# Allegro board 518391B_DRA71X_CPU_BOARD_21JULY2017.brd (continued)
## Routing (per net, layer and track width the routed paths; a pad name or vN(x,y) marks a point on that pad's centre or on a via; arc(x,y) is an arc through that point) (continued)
H_DDR1_D13: length 31.5
  TOP w0.102: U23.D7 v4(62.55,93)
  TOP w0.127: v2(78.63,90.33) 78.65,90.33 78.77,90.45 79.98,90.45 80.09,90.56 U27.AB25
  LY4 w0.133: v4(62.55,93) 62.55,93.36 62.8,93.61 62.8,93.95 62.55,94.2 62.55,94.45 62.84,94.74 63.09,94.74 63.45,94.39 63.88,94.39 64.24,94.74 64.59,94.74 64.9,94.44 65.43,94.44 65.74,94.74 66.01,94.74 66.32,94.44 66.32,94.09 66.45,93.95 70.23,93.95 71.98,92.2 71.98,90.83 71.53,90.37 71.53,90.12 71.66,89.99 72.41,89.99 72.54,90.12 72.54,90.75 72.68,90.88 72.92,90.88 73.04,90.77 73.04,90.34 73.15,90.22 73.43,90.22 73.58,90.37 73.58,90.55 73.89,90.86 74.16,90.86 74.59,90.42 78.11,90.42 78.2,90.33 v2(78.63,90.33)
H_DDR1_D14: length 31.2
  TOP w0.102: U23.A3 v4(64.95,97)
  TOP w0.127: v2(80.01,90.02) 80.33,89.7 81.29,89.7 81.5,89.91 U27.AA25
  LY4 w0.133: v4(64.95,97) 65.36,97.41 65.67,97.41 65.8,97.28 65.8,96.91 65.93,96.77 66.2,96.77 66.33,96.91 66.33,97.28 66.46,97.41 66.72,97.41 66.86,97.28 66.86,96.91 66.99,96.77 67.25,96.77 67.38,96.91 67.38,97.28 67.52,97.41 67.78,97.41 67.91,97.28 67.91,96.91 68.04,96.77 68.31,96.77 68.44,96.91 68.44,97.28 68.57,97.41 68.84,97.41 68.97,97.28 68.97,96.91 69.1,96.77 69.37,96.77 69.5,96.91 69.5,97.28 69.63,97.41 69.89,97.41 70.03,97.28 70.03,96.91 70.16,96.77 70.42,96.77 70.55,96.91 70.55,97.28 70.69,97.41 74.8,97.41 75.01,97.21 75.01,96.8 75.14,96.67 76.48,96.67 76.68,96.47 76.68,95.63 77.37,94.95 77.37,94.08 78.36,93.09 78.46,93.09 79.63,91.92 79.63,91.14 80.01,90.75 v2(80.01,90.02)
H_DDR1_D15: length 31.2
  TOP w0.102: U27.W24 85.49,88.29 85.49,88.28 84.4,88.28 ; U23.C2 v4(63.35,97.8)
  TOP w0.127: v2(81,88.16) 81.42,88.16 81.55,88.28 84.4,88.28
  LY4 w0.133: v4(63.35,97.8) 63.75,98.19 76.89,98.19 78.36,96.72 78.36,95.12 81.28,92.2 81.28,88.44 v2(81,88.16)
H_DDR1_D16: length 39.3
  TOP w0.102: U29.F8 v4(60.95,77.97)
  TOP w0.127: U27.W23 v1(86.14,88.28)
  LY4 w0.133: v4(60.95,77.97) 60.55,78.37 59.16,78.37 58.88,78.65 58.88,79.68 58.42,80.14 58.42,84.84 60.64,87.06 65.17,87.06 65.87,87.76 71.93,87.76 72.14,87.96 80.01,87.96 80.55,87.42 81.69,87.42 82.54,88.27 v1(86.14,88.28)
H_DDR1_D17: length 44
  TOP w0.102: U29.H8 v4(59.35,77.97)
  TOP w0.127: v2(74.55,84.07) 74.55,85.82 74.94,86.21 75.92,86.21 76.2,85.93 76.7,85.93 77.3,86.53 81.2,86.53 81.2,86.52 81.55,86.52 81.56,86.53 82.44,86.53 83.22,87.31 U27.U25
  LY3 w0.133: v2(74.55,84.07) 74.34,83.87 74.34,82.6 74.04,82.3 73.61,82.3 73.33,82.58 73.33,83.06 73.1,83.29 69.85,83.29 69.67,83.11 69.67,82.53 69.47,82.32 68.95,82.32 68.67,82.6 68.67,83.02 68.5,83.19 67.94,83.19 67.67,82.91 67.67,82.4 67.26,81.99 66.17,81.99 65.91,81.74 62.89,81.74 62.43,82.19 59.41,82.19 59.08,81.86 59.08,79.51 59.24,79.35 59.56,79.35 59.72,79.51 59.72,81.61 59.87,81.76 60.17,81.76 60.33,81.61 60.33,79.61 59.75,79.03 59.75,78.37 v4(59.35,77.97)
H_DDR1_D18: length 44.5
  TOP w0.102: U29.F7 v4(60.95,78.77) ; 84.4,86.98 85.49,86.98 85.49,86.99 U27.U24
  TOP w0.127: 84.4,86.98 83.38,86.98 82.67,86.28 81.67,86.28 81.66,86.27 81.1,86.27 81.09,86.28 77.54,86.28 76.94,85.68 75.97,85.68 75.72,85.93 75.34,85.93 75.13,85.72 75.13,84.91 75.21,84.84 75.44,84.84 75.9,85.29 76.2,85.29 76.3,85.19 76.3,85.04 75.09,83.83 75.09,82.2 v2(74.55,81.66)
  LY3 w0.133: v4(60.95,78.77) 60.55,78.37 60.55,76.84 60.83,76.56 62.74,76.56 62.94,76.76 62.94,77.01 62.94,77.01 62.94,78.94 62.94,78.94 62.94,79.13 62.74,79.33 62.74,80.67 63.12,81.05 66.42,81.05 66.75,81.38 67.87,81.38 68.15,81.66 70.35,81.66 70.48,81.53 70.48,81.2 70.38,81.1 69.01,81.1 68.81,80.9 68.81,80.72 69.01,80.52 72.52,80.52 72.75,80.75 74.27,80.75 74.55,81.03 v2(74.55,81.66)
H_DDR1_D19: length 42.8
  TOP w0.102: U29.F2 v4(60.95,83.57)
  TOP w0.127: U27.W21 v1(87.44,88.28)
  LY3 w0.133: v4(60.95,83.57) 60.54,83.97 60.54,84.8 61.09,85.34 61.09,86.05 61.62,86.58 61.62,88.24 62.41,89.03 64.49,89.03 65.27,89.8 65.6,89.8 65.73,89.67 65.73,89.34 65.87,89.2 66.13,89.2 66.26,89.34 66.26,89.67 66.39,89.8 66.66,89.8 66.79,89.67 66.79,89.34 66.92,89.2 67.19,89.2 67.32,89.34 67.32,89.67 67.51,89.87 70.94,89.87 71.57,89.24 79.14,89.24 79.65,88.72 80.19,88.72 80.32,88.85 80.32,89.5 80.46,89.64 80.72,89.64 80.85,89.5 80.85,88.85 80.98,88.72 81.25,88.72 81.38,88.85 81.38,89.5 81.51,89.64 81.78,89.64 81.91,89.5 81.91,88.85 82.04,88.72 82.3,88.72 82.44,88.85 82.44,89.5 82.57,89.64 82.83,89.64 82.96,89.5 82.96,88.85 83.1,88.72 83.36,88.72 83.49,88.85 83.49,89.5 83.62,89.64 83.89,89.64 84.02,89.5 84.02,88.85 84.15,88.72 84.42,88.72 84.55,88.85 84.55,89.5 84.68,89.64 84.95,89.64 85.08,89.5 85.08,88.91 85.21,88.78 86.95,88.78 v1(87.44,88.28)
H_DDR1_D20: length 42.4
  TOP w0.102: U29.E3 v4(61.75,82.77)
  TOP w0.127: U27.T22 v1(86.79,86.33)
  LY3 w0.133: v1(86.79,86.33) 87.16,86.71 87.59,86.71 87.82,86.93 87.82,87.12 87.69,87.25 87,87.25 86.49,86.74 85.25,86.74 85.12,86.87 85.12,87.29 84.98,87.43 84.61,87.43 84.4,87.22 84.4,86.51 84.21,86.31 83.94,86.31 83.77,86.49 83.77,87.35 83.67,87.45 83.35,87.45 83.22,87.32 83.22,86.52 83.09,86.39 82.82,86.39 82.55,86.66 82.55,87.13 82.23,87.45 81.8,87.45 81.72,87.36 81.11,87.36 81,87.25 80.39,87.25 80.14,86.99 78.69,86.99 78.56,87.13 78.56,87.31 78.66,87.41 79.27,87.41 79.4,87.54 79.4,87.73 79.28,87.85 72.84,87.85 72.45,87.46 65.97,87.46 65.34,86.83 63.85,86.83 63.63,86.62 63.63,85.07 63.48,84.91 63.3,84.91 63.17,85.04 63.17,86.61 63.02,86.76 62.84,86.76 62.59,86.51 62.59,85.55 62.15,85.11 62.15,83.17 v4(61.75,82.77)
H_DDR1_D21: length 42.5
  TOP w0.102: U29.G2 v4(60.15,83.57)
  TOP w0.127: U27.U22 v1(86.79,87.63)
  LY3 w0.133: v1(86.79,87.63) 86.33,87.17 85.83,87.17 84.81,88.19 81.87,88.19 81.74,88.06 81.74,87.84 81.61,87.71 80.11,87.71 79.65,88.17 72.57,88.17 72.14,87.73 70.98,87.73 70.85,87.86 70.85,88.77 70.72,88.9 70.45,88.9 70.32,88.77 70.32,87.86 70.19,87.73 69.93,87.73 69.79,87.86 69.79,88.77 69.66,88.9 69.4,88.9 69.27,88.77 69.27,87.86 69.13,87.73 68.87,87.73 68.74,87.86 68.74,88.77 68.61,88.9 68.34,88.9 68.21,88.77 68.21,87.86 68.08,87.73 67.81,87.73 67.68,87.86 67.68,88.77 67.55,88.9 67.28,88.9 67.15,88.77 67.15,87.86 67.02,87.73 66.76,87.73 66.62,87.86 66.62,88.77 66.49,88.9 66.23,88.9 66.1,88.77 66.1,88 65.19,87.1 62.63,87.1 61.35,85.81 61.35,83.39 61.13,83.17 60.55,83.17 v4(60.15,83.57)
H_DDR1_D22: length 39.1
  TOP w0.102: U29.H7 v4(59.35,78.77)
  TOP w0.127: U27.U23 v1(86.14,87.63)
  LY4 w0.133: v1(86.14,87.63) 85.7,87.19 85.41,87.19 85.23,87.37 85.23,87.8 85.07,87.96 84.86,87.96 84.7,87.8 84.7,87.28 84.57,87.15 84.28,87.15 84.1,87.33 84.1,87.68 83.97,87.81 83.49,87.81 83.34,87.66 83.34,86.89 82.89,86.45 80.89,86.45 79.68,87.66 72.42,87.66 72.23,87.47 66,87.47 65.22,86.69 60.75,86.69 58.8,84.73 58.8,80.39 59.35,79.84 v4(59.35,78.77)
H_DDR1_D23: length 39.2
  TOP w0.102: U29.H3 v4(59.35,82.77)
  TOP w0.127: U27.T21 v1(87.44,86.33)
  LY4 w0.133: v1(87.44,86.33) 87.03,86.74 84.68,86.74 83.42,85.47 83.23,85.47 83.05,85.65 82.86,85.65 82.67,85.47 82.67,85.28 82.85,85.1 82.85,84.91 82.67,84.72 81.4,84.72 81.27,84.86 81.27,85.29 81.14,85.42 80.87,85.42 80.74,85.29 80.74,84.86 80.61,84.72 80.34,84.72 80.21,84.86 80.21,85.29 80.08,85.42 79.82,85.42 79.68,85.29 79.68,84.86 79.55,84.72 79.29,84.72 79.16,84.86 79.16,85.29 79.02,85.42 78.76,85.42 78.63,85.29 78.63,84.86 78.49,84.72 78.23,84.72 78.1,84.86 77.57,84.86 77.44,84.72 67.81,84.72 67.45,84.37 67.45,81.78 66.45,80.77 59.66,80.77 59.35,81.09 v4(59.35,82.77)
H_DDR1_D24: length 31.3
  TOP w0.102: U29.C3 v4(63.35,82.77)
  TOP w0.127: U27.T23 v1(86.14,86.33)
  LY3 w0.133: v4(63.35,82.77) 62.95,83.17 62.95,83.75 63.16,83.97 64.38,83.97 64.55,84.14 64.55,84.59 64.77,84.81 65.15,84.81 65.28,84.94 65.28,85.33 65.14,85.46 64.75,85.46 64.54,85.67 64.54,86.18 64.92,86.57 66.51,86.57 67.07,87.12 72.57,87.12 72.92,87.48 75.69,87.48 75.92,87.25 75.92,86.92 76.05,86.79 76.68,86.79 76.89,86.99 76.89,87.33 77.09,87.53 77.7,87.53 77.93,87.3 77.93,86.66 78.08,86.51 82.14,86.51 82.65,86 84.43,86 84.75,86.33 v1(86.14,86.33)
H_DDR1_D25: length 32.6
  TOP w0.102: U29.A7 v4(64.95,78.77)
  TOP w0.127: U27.T25 84.42,86.66 84.35,86.59 83.36,86.59 82.8,86.02 81.77,86.02 81.76,86.01 80.99,86.01 80.98,86.02 77.77,86.02 75.69,83.95 v2(75.69,82.68)
  LY3 w0.133: v4(64.95,78.77) 65.27,79.1 66.74,79.1 66.87,79.23 66.87,79.67 67,79.81 67.27,79.81 67.4,79.67 67.4,79.23 67.53,79.1 67.8,79.1 67.93,79.23 67.93,79.67 68.06,79.81 68.32,79.81 68.46,79.67 68.46,79.23 68.59,79.1 68.85,79.1 68.98,79.23 68.98,79.67 69.12,79.81 69.38,79.81 69.51,79.67 69.51,79.23 69.64,79.1 69.91,79.1 70.04,79.23 70.04,79.67 70.17,79.81 70.44,79.81 70.57,79.67 70.57,79.23 70.7,79.1 70.97,79.1 71.1,79.23 71.1,79.67 71.23,79.81 71.49,79.81 71.63,79.67 71.63,79.23 71.76,79.1 72.02,79.1 72.15,79.23 72.15,79.67 72.29,79.81 72.55,79.81 72.68,79.67 72.68,79.23 72.81,79.1 74.02,79.1 75.18,80.26 75.18,82.17 v2(75.69,82.68)
H_DDR1_D26: length 32.6
  TOP w0.102: U29.B8 v4(64.15,77.97) ; 84.4,86.33 85.49,86.33 U27.T24
  TOP w0.127: v2(75.68,81.8) 76.2,82.32 76.2,84.1 77.87,85.77 80.88,85.77 80.89,85.76 81.87,85.76 81.88,85.77 82.95,85.77 83.51,86.33 84.4,86.33
  LY3 w0.133: v4(64.15,77.97) 64.55,77.57 66.71,77.57 66.85,77.7 66.85,77.87 66.98,78 67.25,78 67.38,77.87 67.38,77.19 67.51,77.06 67.78,77.06 67.91,77.19 67.91,77.87 68.05,78 68.31,78 68.45,77.87 68.45,77.7 68.58,77.57 68.85,77.57 68.98,77.7 68.98,77.87 69.11,78 69.38,78 69.51,77.87 69.51,77.7 69.65,77.57 69.91,77.57 70.05,77.7 70.05,77.87 70.18,78 70.45,78 70.58,77.87 70.58,77.7 70.71,77.57 70.98,77.57 71.11,77.7 71.11,77.87 71.25,78 71.51,78 71.65,77.87 71.65,77.7 71.78,77.57 72.05,77.57 72.18,77.7 72.18,77.87 72.31,78 72.58,78 72.71,77.87 72.71,77.7 72.85,77.57 73.25,77.57 75.68,80 v2(75.68,81.8)
H_DDR1_D27: length 31.2
  TOP w0.102: U29.A3 v4(64.95,82.77)
  TOP w0.127: U27.P21 v1(87.44,85.68)
  LY3 w0.133: v4(64.95,82.77) 65.61,82.77 67.26,84.42 67.26,84.79 67.69,85.22 69.46,85.22 69.6,85.35 69.6,85.54 69.43,85.71 67.52,85.71 67.39,85.84 67.39,86.02 67.52,86.16 72.11,86.16 72.29,85.98 72.29,85.45 72.57,85.17 77.27,85.17 77.72,85.62 81.48,85.62 82.08,85.02 86.78,85.02 v1(87.44,85.68)
H_DDR1_D28: length 28.2
  TOP w0.102: U29.C8 v4(63.35,77.97)
  TOP w0.127: U27.N21 v1(87.44,84.38)
  LY4 w0.133: v4(63.35,77.97) 64.02,78.37 65.06,78.37 66.41,78.87 74.68,78.87 80.01,84.2 82.8,84.2 83.7,85.09 86.73,85.09 v1(87.44,84.38)
H_DDR1_D29: length 31.3
  TOP w0.102: U29.C2 v4(63.35,83.57)
  TOP w0.127: U27.P22 v1(86.79,85.68)
  LY3 w0.133: v1(86.79,85.68) 86.4,85.28 82.36,85.28 81.71,85.93 77.52,85.93 77.24,85.65 72.92,85.65 72.8,85.78 72.8,85.93 72.92,86.06 74.3,86.06 74.45,86.21 74.45,86.36 74.31,86.5 67.3,86.5 66.93,86.13 66.93,84.54 65.56,83.17 63.75,83.17 v4(63.35,83.57)
H_DDR1_D30: length 31.3
  TOP w0.102: U29.A2 v4(64.95,83.57)
  TOP w0.127: U27.P23 v1(86.14,85.68)
  LY3 w0.133: v4(64.95,83.57) 65.56,83.57 66.6,84.61 66.6,85.75 66.47,85.88 66.22,85.88 66.09,85.75 66.09,84.8 65.92,84.63 65.74,84.63 65.58,84.79 65.58,85.87 66,86.29 66.62,86.29 67.15,86.82 72.9,86.82 73.23,87.15 75.41,87.15 75.56,86.99 75.56,86.66 75.46,86.56 74.96,86.56 74.85,86.46 74.85,86.06 75,85.91 76.99,85.91 77.32,86.23 81.94,86.23 82.43,85.74 v1(86.14,85.68)
H_DDR1_D31: length 29.2
  TOP w0.102: 84.4,84.82 84.62,85.03 85.49,85.03 U27.P24 ; U29.D7 v4(62.55,78.77)
  TOP w0.127: v2(77.45,83.29) 77.98,83.82 78.49,83.82 79.12,84.45 84.04,84.45 84.4,84.82
  LY4 w0.133: v4(62.55,78.77) 62.55,79.67 62.99,80.11 67.08,80.11 67.74,80.77 67.74,81.25 68.68,82.19 68.68,82.91 69.16,83.39 71.04,83.39 71.5,82.93 71.5,82.49 71.69,82.3 73.03,82.3 73.28,82.55 73.28,82.93 73.64,83.29 v2(77.45,83.29)
H_DDR1_DQM0: length 33.4
  TOP w0.102: U23.E7 v4(61.75,93)
  TOP w0.127: U27.AE23 86.46,93.37 85.45,94.39 v2(84.15,94.39)
  LY3 w0.133: v2(84.15,94.39) 85.47,94.39 85.62,94.24 85.62,93.55 85.49,93.42 84.18,93.42 83.41,92.66 83.41,91.82 83.06,91.47 82.4,91.47 81.66,92.2 80.92,92.2 80.49,91.77 79.45,91.77 77.6,93.62 61.9,93.62 61.75,93.47 v4(61.75,93)
H_DDR1_DQM1: length 30.7
  TOP w0.102: U23.D3 v4(62.55,97)
  TOP w0.127: U27.W22 v1(86.79,88.28)
  LY4 w0.133: v1(86.79,88.28) 86.29,88.79 82.42,88.79 81.35,87.72 80.84,87.72 79.45,89.1 79.45,90.12 78.79,90.78 77.62,90.78 77.22,91.19 77.22,91.41 72.72,95.91 63.2,95.91 62.55,96.56 v4(62.55,97)
H_DDR1_DQM2: length 42.4
  TOP w0.102: U29.E7 v4(61.75,78.77)
  TOP w0.127: U27.U21 v1(88.09,87.63)
  LY3 w0.133: v1(88.09,87.63) 88.27,87.46 88.27,86.68 88.46,86.49 88.46,85.53 87.72,84.79 84.54,84.79 84.51,84.76 82.6,84.76 81.72,83.88 75.63,83.88 74.8,83.06 74.8,82.54 73.87,81.6 72.76,81.6 72.34,81.18 71.08,81.18 70.94,81.31 70.94,81.58 71.08,81.71 72.03,81.71 72.14,81.81 72.14,82.06 72,82.19 70.03,82.19 69.77,81.94 67.82,81.94 67.56,81.69 66.4,81.69 66.07,81.36 62.71,81.36 62.23,81.84 60.83,81.84 60.73,81.74 60.73,80.92 60.91,80.75 61.75,80.75 61.88,80.61 61.88,80.37 61.74,80.23 60.98,80.23 60.79,80.04 60.79,79.76 60.92,79.63 61.54,79.63 61.75,79.43 v4(61.75,78.77)
H_DDR1_DQM3: length 32.1
  TOP w0.102: U29.D3 v4(62.55,82.77)
  TOP w0.127: v2(78.13,84.3) 78.66,84.84 83.9,84.84 84.42,85.36 U27.P25
  LY3 w0.133: v4(62.55,82.77) 63.23,82.09 65.63,82.09 68.25,84.71 77.52,84.71 77.98,85.17 81.1,85.17 81.23,85.03 81.23,84.43 81.1,84.3 v2(78.13,84.3)
H_DDR1_DQS0_N: length 33.4
  TOP w0.102: v2(84.63,95.55) 84.86,95.33 85.55,95.33 87.12,93.76 87.12,92.79 87.12,92.78 87.12,92.51 U27.AE22
  TOP w0.103: U23.G3 v4(60.15,97)
  LY3 w0.102: 85.17,95.43 85.06,95.33 84.86,95.33 v2(84.63,95.55)
  LY3 w0.114: 85.17,95.43 85.17,95.74 84.92,95.99 84.45,95.99 84.18,95.71 83.9,95.71 83.62,95.99 82.93,95.99 82.68,95.73 82.4,95.73 82.14,95.99 78.96,95.99 77.8,94.82 67.7,94.82 67.19,95.33 61.01,95.33 60.35,95.99 60.35,96.79 v4(60.15,97)
H_DDR1_DQS0_P: length 33.7
  TOP w0.102: v2(84.66,94.82) 84.89,95.05 85.36,95.05 86.79,93.62 86.79,92.78
  TOP w0.103: 86.79,92.78 86.79,92.37 87.11,92.04 U27.AD22 ; U23.F3 v4(60.95,97)
  LY3 w0.102: v2(84.66,94.82) 84.66,94.84 84.86,95.05 85.24,95.05
  LY3 w0.114: v4(60.95,97) 60.71,96.75 60.71,96.13 61.16,95.68 67.34,95.68 67.84,95.17 77.65,95.17 78.82,96.34 85.06,96.34 85.47,95.94 85.47,95.28 85.24,95.05
H_DDR1_DQS1_N: length 31.2
  TOP w0.102: U27.Y25 85.16,89.26 84.89,89.26 84.89,89.26 82.17,89.26 82.17,89.26 81.85,89.26 81.72,89.13 80.42,89.13 80.41,89.13 79.23,89.13 v2(78.92,88.82)
  TOP w0.103: U23.B7 v4(64.15,93)
  LY4 w0.114: v4(64.15,93) 63.91,93.24 63.91,93.47 64.03,93.6 65.26,93.6 65.8,93.06 69.92,93.06 71.01,91.96 71.01,91.1 70.36,90.45 69.65,90.45 69.04,89.84 69.04,88.83 69.63,88.24 70.81,88.24 71.72,89.15 72.09,89.15 72.44,88.8 72.75,88.8 73.1,89.15 73.38,89.15 73.66,88.88 73.82,88.88 74.09,89.15 74.3,89.15 74.57,88.88 74.73,88.88 75.01,89.15 78.13,89.15 78.2,89.08 78.36,89.08 78.44,89.15 78.58,89.15 v2(78.92,88.82)
H_DDR1_DQS1_P: length 31.7
  TOP w0.102: U27.Y24 85.49,89.59 85.03,89.59 85.03,89.59 82.03,89.59 82.03,89.59 81.71,89.59 81.58,89.46 79.93,89.46 79.93,89.46 79.15,89.46 v2(78.92,89.7)
  TOP w0.103: U23.C7 v4(63.35,93)
  LY4 w0.114: v2(78.92,89.7) 78.73,89.51 71.58,89.51 70.66,88.6 69.77,88.6 69.39,88.98 69.39,89.69 69.79,90.09 70.51,90.09 71.36,90.95 71.36,92.11 70.06,93.41 65.95,93.41 65.4,93.95 63.89,93.95 63.55,93.62 63.55,93.2 v4(63.35,93)
H_DDR1_DQS2_N: length 40.3
  TOP w0.102: 84.4,87.95 84.43,87.97 84.72,87.97 84.73,87.97 85.15,87.97 U27.V25
  TOP w0.103: U29.G3 v4(60.15,82.77)
  TOP w0.112: v2(76.38,87.23) 77.15,87.23 77.27,87.35 80.54,87.35 80.91,87.72 81.62,87.72 81.83,87.92 84.38,87.92 84.4,87.95
  LY4 w0.114: v2(76.38,87.23) 77.11,87.23 77.72,86.61 77.72,85.82 77.17,85.27 74.42,85.27 74.1,85.59 74.1,86.19 73.99,86.31 73.76,86.31 73.64,86.19 73.64,85.59 73.32,85.27 72.8,85.27 72.48,85.59 72.48,86.19 72.36,86.31 72.13,86.31 72.02,86.19 72.02,85.59 71.7,85.27 71.17,85.27 70.85,85.59 70.85,86.19 70.74,86.31 70.51,86.31 70.39,86.19 70.39,85.59 70.07,85.27 69.55,85.27 69.23,85.59 69.23,86.19 69.03,86.39 68.1,86.39 66.42,84.71 66.42,82.05 65.68,81.31 60.55,81.31 60.15,81.71 v4(60.15,82.77)
H_DDR1_DQS2_P: length 40.5
  TOP w0.102: 85.49,87.64 85.49,87.63 85.33,87.63 85.32,87.62 85.31,87.62 85.31,87.62 85.29,87.62
  TOP w0.103: U27.V24 85.49,87.64 ; U29.F3 v4(60.95,82.77)
  TOP w0.112: v2(76.38,86.35) 76.38,86.69 76.51,86.82 76.55,86.82 76.6,86.88 77.3,86.88 77.41,86.99 80.69,86.99 81.06,87.36 81.77,87.36 81.97,87.57 84.53,87.57 84.58,87.62 85.29,87.62
  LY4 w0.114: v2(76.38,86.35) 76.38,86.66 76.59,86.88 76.96,86.88 77.37,86.47 77.37,85.97 77.03,85.62 74.57,85.62 74.46,85.74 74.46,86.34 74.13,86.66 73.61,86.66 73.29,86.34 73.29,85.74 73.17,85.62 72.95,85.62 72.83,85.74 72.83,86.34 72.51,86.66 71.99,86.66 71.66,86.34 71.66,85.74 71.55,85.62 71.32,85.62 71.21,85.74 71.21,86.34 70.88,86.66 70.36,86.66 70.04,86.34 70.04,85.74 69.92,85.62 69.7,85.62 69.58,85.74 69.58,86.34 69.18,86.74 67.95,86.74 66.07,84.86 66.07,82.19 65.53,81.66 60.7,81.66 60.5,81.86 60.5,82.6 60.67,82.77 v4(60.95,82.77)
H_DDR1_DQS3_N: length 29.6
  TOP w0.102: U27.R25 85.16,86 84.4,86
  TOP w0.103: U29.B7 v4(64.15,78.77)
  TOP w0.112: v2(73.69,81.18) 73.94,80.93 75.54,80.93 76.61,81.99 76.61,83.87 78.25,85.51 83.38,85.51 83.87,86 84.4,86
  LY4 w0.114: v4(64.15,78.77) 63.93,78.99 63.93,79.18 64.05,79.3 74.52,79.3 75.03,79.81 75.03,80.54 74.65,80.93 73.94,80.93 v2(73.69,81.18)
H_DDR1_DQS3_P: length 29.8
  TOP w0.102: U27.R24 85.49,85.69 84.58,85.69 84.54,85.65 84.4,85.65
  TOP w0.103: U29.C7 v4(63.35,78.77)
  TOP w0.112: 84.4,85.65 84.02,85.65 83.53,85.16 78.4,85.16 76.96,83.72 76.96,81.84 75.69,80.57 73.94,80.57 v2(73.69,80.32)
  LY4 w0.114: v4(63.35,78.77) 63.58,79 63.58,79.33 63.9,79.65 74.38,79.65 74.68,79.95 74.68,80.4 74.5,80.57 73.94,80.57 v2(73.69,80.32)
H_DDR1_ODT0: length 103.1
  TOP w0.102: U29.K1 v4(56.95,84.37) ; 90.04,93.24 90.04,92.18 U27.AD18 ; U23.K1 v4(56.95,98.6)
  TOP w0.127: 90.04,93.24 90.04,94.49 89.12,95.41 89.12,96.76 89,96.88 v2(89,98.98)
  LY3 w0.133: v2(89,98.98) 89,97.99 88.77,97.76 87.08,97.76 85.73,99.11 85.73,99.73 85.16,100.29 83.63,100.29 83.02,100.91 82.07,100.91 81.93,100.77 81.93,99.8 81.8,99.66 81.53,99.66 81.4,99.8 81.4,100.77 81.27,100.91 81,100.91 80.87,100.77 80.87,99.8 80.73,99.66 80.47,99.66 80.33,99.8 80.33,100.77 80.2,100.91 79.93,100.91 79.8,100.77 79.8,99.8 79.67,99.66 79.4,99.66 79.27,99.8 79.27,100.77 79.13,100.91 78.87,100.91 78.73,100.77 78.73,99.8 78.6,99.66 78.33,99.66 78.2,99.8 78.2,100.57 77.94,100.84 76.81,100.84 76.67,100.7 76.67,99.8 76.54,99.66 76.27,99.66 76.14,99.8 76.14,100.7 76.01,100.84 75.74,100.84 75.61,100.7 75.61,99.8 75.47,99.66 75.21,99.66 75.07,99.8 75.07,100.7 74.94,100.84 74.67,100.84 74.54,100.7 74.54,99.8 74.41,99.66 74.14,99.66 74.01,99.8 74.01,100.7 73.87,100.84 73.61,100.84 73.47,100.7 73.47,99.8 73.34,99.66 73.07,99.66 72.94,99.8 72.94,100.7 72.81,100.84 69.68,100.84 69.55,100.7 69.55,100.13 69.42,99.99 69.15,99.99 69.02,100.13 69.02,100.7 68.88,100.84 68.62,100.84 68.48,100.7 68.48,100.13 68.35,99.99 68.08,99.99 67.95,100.13 67.95,100.7 67.82,100.84 67.55,100.84 67.42,100.7 67.42,100.13 67.28,99.99 67.02,99.99 66.88,100.13 66.88,100.7 66.75,100.84 66.48,100.84 66.35,100.7 66.35,100.13 66.22,99.99 65.95,99.99 65.82,100.13 65.82,100.7 65.68,100.84 59.66,100.84 59.53,100.7 59.53,100.01 59.39,99.88 59.13,99.88 58.99,100.01 58.99,100.7 58.86,100.84 58.59,100.84 58.46,100.7 58.46,100.01 58.33,99.88 58.06,99.88 57.93,100.01 57.93,100.7 57.79,100.84 57.41,100.84 56.95,100.37 v4(56.95,98.6)
  LY4 w0.133: v4(56.95,98.6) 57.35,97.92 57.35,94.57 58.19,93.73 58.19,91.62 56.95,90.37 56.95,90.11 57.08,89.98 57.47,89.98 57.61,89.85 57.61,89.58 57.47,89.45 57.08,89.45 56.95,89.31 v4(56.95,84.37) 57.35,83.97 57.35,80 58.17,79.18 58.17,78.1 58.42,77.85 58.42,75.57 59.04,74.94 60.8,74.94 62.36,73.38 v2(62.36,73.02)
  BOTTOM w0.127: R276.2 v2(62.36,73.02)
H_DDR1_RASN: length 109.8
  TOP w0.102: U27.AD17 90.69,92.18 90.69,92.96 90.64,93 90.64,93.24 ; U29.J3 v4(57.75,82.77) ; U23.J3 v4(57.75,97)
  TOP w0.127: v2(88.32,101.5) 88.32,100.15 88.8,99.67 89.61,99.67 90.27,99.01 90.27,97.99 89.74,97.46 89.74,95.73 90.64,94.83 90.64,93.24 ; R96.2 v2(62.99,72.58)
  LY4 w0.133: v2(62.99,72.58) 62.99,73.18 60.96,75.21 60.35,75.21 58.93,76.63 58.93,77.98 58.62,78.29 58.62,79.28 57.75,80.15 v4(57.75,82.77)
  BOTTOM w0.127: v4(57.75,82.77) 58.28,83.3 58.28,83.91 58.93,84.56 58.93,86.89 58.14,87.68 58.14,91.31 58.39,91.57 58.39,93.42 58.95,93.98 61.87,93.98 62.26,94.36 62.26,95.5 61.82,95.94 58.81,95.94 v4(57.75,97) 58.15,97.4 58.15,98.95 58.53,99.33 59.74,99.33 60.14,99.73 60.14,101.91 60.52,102.29 65.83,102.29 66.35,101.77 66.35,101.15 66.48,101.02 66.74,101.02 66.86,100.89 66.86,100.27 66.99,100.15 67.24,100.15 67.37,100.27 67.37,100.89 67.5,101.02 67.75,101.02 67.88,100.89 67.88,100.27 68.01,100.15 68.26,100.15 68.39,100.27 68.39,100.89 68.51,101.02 68.77,101.02 68.89,100.89 68.89,100.27 69.02,100.15 69.28,100.15 69.4,100.27 69.4,100.89 69.53,101.02 69.78,101.02 69.91,100.89 69.91,100.27 70.04,100.15 70.29,100.15 70.42,100.27 70.42,100.89 70.55,101.02 70.8,101.02 70.93,100.89 70.93,100.27 71.05,100.15 71.31,100.15 71.43,100.27 71.43,100.89 71.56,101.02 71.82,101.02 71.94,100.89 71.94,100.27 72.07,100.15 72.32,100.15 72.45,100.27 72.45,100.89 72.58,101.02 72.83,101.02 72.96,100.89 72.96,100.27 73.09,100.15 73.34,100.15 73.47,100.27 73.47,100.89 73.59,101.02 73.85,101.02 73.97,100.89 73.97,100.27 74.1,100.15 74.36,100.15 74.48,100.27 74.48,100.89 74.61,101.02 74.86,101.02 74.99,100.89 74.99,100.27 75.12,100.15 75.37,100.15 75.5,100.27 75.5,100.89 75.63,101.02 75.88,101.02 76.01,100.89 76.01,100.27 76.13,100.15 76.39,100.15 76.51,100.27 76.51,100.89 76.64,101.02 76.9,101.02 77.02,100.89 77.02,100.27 77.15,100.15 77.4,100.15 77.53,100.27 77.53,100.89 77.66,101.02 77.91,101.02 78.04,100.89 78.04,100.27 78.17,100.15 78.42,100.15 78.55,100.27 78.55,100.89 78.67,101.02 78.93,101.02 79.05,100.89 79.05,100.27 79.18,100.15 79.44,100.15 79.56,100.27 79.56,100.89 79.69,101.02 79.94,101.02 80.07,100.89 80.07,100.27 80.2,100.15 80.45,100.15 80.58,100.27 80.58,100.89 80.71,101.02 80.96,101.02 81.09,100.89 81.09,100.27 81.21,100.15 81.47,100.15 81.59,100.27 81.59,100.89 81.72,101.02 81.98,101.02 82.1,100.89 82.1,100.27 82.23,100.15 82.48,100.15 82.61,100.27 82.61,100.89 82.74,101.02 82.99,101.02 83.12,100.89 83.12,100.27 83.25,100.15 83.5,100.15 83.63,100.27 83.63,100.89 83.75,101.02 84.01,101.02 84.13,101.15 84.13,101.77 84.26,101.89 85.37,101.89 85.45,101.97 87.22,101.97 87.69,101.5 v2(88.32,101.5)
H_DDR1_RST: length 74.6
  TOP w0.102: U29.T2 v4(52.15,83.57) ; U23.T2 v4(52.15,97.8)
  TOP w0.127: v2(87.86,102.29) 87.86,100.23 88.67,99.42 89.48,99.42 90.02,98.88 90.02,98.17 89.42,97.57 89.42,95.59 90.36,94.65 U27.AE17
  LY3 w0.133: v2(87.86,102.29) 87.26,102.29 86.47,103.08 84.62,103.08 82.7,104.99 53.76,104.99 52.55,103.78 52.55,98.2 v4(52.15,97.8) 52.55,97.39 52.55,96.72 52.32,96.49 50.27,96.49 49.89,96.11 49.89,84.2 50.52,83.57 v4(52.15,83.57)
H_DDR1_WEN: length 111.7
  TOP w0.102: U23.L3 v4(56.15,97) ; U29.L3 v4(56.15,82.77)
  TOP w0.127: U27.AE18 89.71,94.46 88.86,95.31 88.86,96.66 88.58,96.94 88.58,99.1 87.17,100.51 v2(87.17,103.4)
  BOTTOM w0.127: v2(87.17,103.4) 86.74,103.4 86.56,103.22 83.51,103.22 83.39,103.09 83.39,102.21 83.26,102.09 83.01,102.09 82.88,102.21 82.88,103.09 82.75,103.22 82.5,103.22 82.37,103.09 82.37,102.21 82.24,102.09 81.99,102.09 81.86,102.21 81.86,103.09 81.74,103.22 81.48,103.22 81.36,103.09 81.36,102.21 81.23,102.09 80.97,102.09 80.85,102.21 80.85,103.09 80.72,103.22 80.47,103.22 80.34,103.09 80.34,102.21 80.21,102.09 79.96,102.09 79.83,102.21 79.83,103.09 79.7,103.22 79.45,103.22 79.32,103.09 79.32,102.21 79.2,102.09 78.94,102.09 78.82,102.21 78.82,103.09 78.69,103.22 59.55,103.22 59.42,103.09 59.42,102.15 59.3,102.02 59.04,102.02 58.91,102.15 58.91,103.09 58.79,103.22 58.53,103.22 58.41,103.09 58.41,102.15 58.28,102.02 58.03,102.02 57.9,102.15 57.9,103.09 57.77,103.22 56.88,103.22 56.54,102.88 56.54,101.77 56.67,101.64 59.09,101.64 59.22,101.51 59.22,101.26 59.09,101.13 56.67,101.13 56.54,101 56.54,100.75 56.67,100.62 59.09,100.62 59.22,100.5 59.22,100.24 59.09,100.11 56.67,100.11 56.54,99.99 56.54,97.39 v4(56.15,97) 56.15,96.32 56.27,96.19 57.07,96.19 57.2,96.06 57.2,95.81 57.07,95.68 56.27,95.68 56.15,95.56 56.15,95.3 56.27,95.18 58.08,95.18 58.21,95.05 58.21,94.79 58.08,94.67 56.27,94.67 56.15,94.54 56.15,93.71 56.54,93.32 56.54,92.69 56.15,92.29 56.15,91.11 56.82,90.44 56.82,90.18 56.69,90.06 56.11,90.06 55.98,89.93 55.98,89.67 56.11,89.55 56.69,89.55 56.82,89.42 56.82,84.89 56.54,84.61 56.54,83.17 v4(56.15,82.77) 56.15,81.52 54.95,80.33 54.95,77.01 58.25,73.72 59.53,73.72 59.64,73.61 60.63,73.61 v2(61.21,73.02) R277.2
H_EHRPWM2A: length 23.1
  TOP w0.127: U24.7 v2(118.24,93.49) ; U27.Y5 v1(98.49,88.93)
  LY3 w0.133: v2(118.24,93.49) 115.59,93.49 114.55,92.46 103.38,92.46 100.55,89.63 99.18,89.63 v1(98.49,88.93)
H_EHRPWM2B: length 25.4
  TOP w0.127: U24.6 v2(117.6,93.99) ; v1(97.19,88.93) U27.Y6
  LY3 w0.133: v2(117.6,93.99) 115.46,93.99 114.55,93.09 108.46,93.09 107.95,93.6 103.25,93.6 102.66,93.01 102.66,92.5 100.02,89.86 98.12,89.86 v1(97.19,88.93)
H_EHRPWM3A: length 24.5
  TOP w0.127: U27.Y3 v1(99.79,88.93) ; v2(117.73,92.46) 117.73,92.84 RJ5.3 117.35,94.49 U24.5
  LY3 w0.133: v2(117.73,92.46) 115.82,92.46 115.06,91.69 105.16,91.69 104.01,90.55 102.87,90.55 101.25,88.93 v1(99.79,88.93)
H_EHRPWM3B: length 26.7
  TOP w0.102: 101.52,89.91 U27.AA1
  TOP w0.127: U24.4 v2(117.6,94.99) RJ5.1 ; v2(117.01,88.68) 114.52,88.68 113.41,89.79 105.92,89.79 105.8,89.91 101.52,89.91
  LY4 w0.133: v2(117.6,94.99) 116.46,93.85 116.46,89.24 v2(117.01,88.68)
H_EMU0: length 53.3
  TOP w0.102: 87.76,78.21 U27.C21
  TOP w0.127: J14.19 117.68,56.09 v2(118.11,56.52) ; v1(87.44,78.53) 87.76,78.21
  LY3 w0.133: v2(95.85,60.71) 95.85,63.16 90.38,68.63 87.21,68.63 86.49,69.35 86.49,71.25 87.25,72.01 87.25,74.04 87.44,74.23 v1(87.44,78.53)
  LY4 w0.133: v2(95.85,60.71) 96.48,60.07 103.76,60.07 104.77,59.05 112.14,59.05 112.94,58.25 117.13,58.25 118.11,57.28 v2(118.11,56.52)
  BOTTOM w0.127: R310.2 118.62,55.5 118.62,56.01 v2(118.11,56.52)
H_EMU1: length 53.1
  TOP w0.102: 87.11,78.21 U27.C22
  TOP w0.127: v1(86.79,78.53) 87.11,78.21 ; J14.21 v2(117.19,55.75)
  LY3 w0.133: v1(86.79,78.53) 86.79,73.58 86,72.8 86,69.47 87.11,68.37 90.26,68.37 95.25,63.37 95.25,57.4 v2(95.38,57.28)
  LY4 w0.133: v2(117.19,55.75) 117.09,55.75 116.71,56.13 116.71,56.9 116.34,57.27 98.19,57.27 98.18,57.28 v2(95.38,57.28)
  BOTTOM w0.127: R311.2 116.97,55.53 v2(117.19,55.75)
H_EMU2: length 30.3
  TOP w0.127: v2(119.18,55.8) J14.13
  LY4 w0.133: v2(119.18,55.8) 119.18,55.81 118.62,56.37 118.62,57.28 117.35,58.55 113.02,58.55 112.25,59.32 106.17,59.32 104.78,60.71 v2(98.93,60.71)
  BOTTOM w0.127: R292.2 v2(98.93,60.71)
H_EMU3: length 49.9
  TOP w0.127: v1(91.99,79.83) 92.31,80.16 U27.F14 ; J14.17 v2(118.18,55.75)
  LY3 w0.133: v2(97.96,58.8) 97.92,58.8 97.41,59.31 97.41,62.74 90.21,69.94 v2(90.21,72.14)
  LY4 w0.102: v1(91.99,79.83) 92.55,79.28 92.55,77.43 92.33,77.22
  LY4 w0.133: v2(90.21,72.14) 90.21,75.89 90.9,76.58 91.69,76.58 92.33,77.22 ; v2(97.96,58.8) 102.62,58.8 103.43,57.99 116.63,57.99 117.65,56.98 117.65,56.81 117.64,56.81 117.64,56.22 118.11,55.75 v2(118.18,55.75)
H_EMU4: length 48.1
  TOP w0.127: v2(117.22,56.52) 116.69,55.98 J14.23 ; U27.F13 v1(93.29,79.83)
  LY4 w0.133: v2(95.76,59.44) 96.39,59.44 98.3,57.53 99.2,57.53 99.21,57.54 116.44,57.54 116.45,57.53 116.59,57.53 117.22,56.9 v2(117.22,56.52)
  BOTTOM w0.127: v2(95.76,59.44) 95.38,59.82 95.38,63.63 92.77,66.23 92.77,76.65 92.36,77.06 92.36,78.9 v1(93.29,79.83)
H_GPIO5_17: length 55.2
  TOP w0.127: U27.P5 v1(98.49,85.68)
  LY3 w0.133: v2(142.88,84.45) 135.76,84.45 133.73,86.49 126.24,86.49 124.7,88.02 121.04,88.02 120.1,87.08 106.24,87.08 106.22,87.06 105.73,87.06 105.16,86.49 99.29,86.49 v1(98.49,85.68)
  BOTTOM w0.127: R424.2 143.13,91.19 143.89,90.42 143.89,85.47 v2(142.88,84.45)
H_HDMI_CLKX: length 70.4
  TOP w0.112: U27.AE9 96.14,93.08 96.14,93.81 114.53,112.2 114.53,134.01 108.89,139.64 108.89,149.94 109.12,150.17 109.34,150.17 109.45,150.28 109.45,150.5 109.34,150.62 109,150.62 108.89,150.73 108.89,150.98 109.12,151.21 FL4.4
H_HDMI_CLKY: length 70.4
  TOP w0.112: FL4.1 108.31,151.21 108.53,150.98 108.53,139.5 114.17,133.86 114.17,112.34 95.78,93.95 95.78,93.23 95.21,92.66 95.21,92.15 U27.AD10
H_HDMI_DX0: length 69.4
  TOP w0.112: FL8.4 106.07,149.5 105.84,149.28 105.84,148.66 105.95,148.54 106.24,148.54 106.35,148.43 106.35,148.21 106.24,148.1 105.95,148.1 105.84,147.99 105.84,139.52 112.12,133.24 112.12,112.37 98.32,98.58 96.06,98.58 94.87,97.39 94.87,94.24 94.27,93.64 94.27,93.24 94.26,93.23 U27.AE11
H_HDMI_DX1: length 70.1
  TOP w0.102: 93.61,93.24 93.61,93.22 93.61,93.22 U27.AE12
  TOP w0.112: FL7.4 102.01,149.5 101.78,149.28 101.78,148.8 101.89,148.69 102.17,148.69 102.29,148.57 102.29,148.35 102.17,148.24 101.89,148.24 101.78,148.13 101.78,140.41 110.24,131.95 110.24,113.11 98.2,101.07 97.74,101.07 97.51,101.3 97.36,101.3 97.2,101.14 97.2,100.98 97.43,100.75 97.43,100.3 97.05,99.92 95.99,99.92 93.85,97.79 93.85,95 93.61,94.76 93.61,93.24
H_HDMI_DX2: length 71.8
  TOP w0.102: 92.37,93.37 92.37,93.3 92.37,93.19 92.31,93.14 U27.AE14
  TOP w0.112: 92.37,93.37 92.38,93.38 92.39,93.39 92.39,93.64 92.39,97.85 93.01,98.47 93.01,98.93 92.87,99.07 92.87,99.23 93.03,99.39 93.19,99.39 93.33,99.24 93.78,99.24 94.44,99.9 94.44,100.35 94.36,100.43 94.36,100.59 94.52,100.74 94.67,100.74 94.75,100.67 95.2,100.67 107.92,113.39 107.92,130.96 98.73,140.15 98.73,150.36 98.84,150.47 99.15,150.47 99.26,150.58 99.26,150.81 99.15,150.92 98.84,150.92 98.73,151.03 98.73,151.31 98.96,151.54 FL3.4
H_HDMI_DY0: length 69.5
  TOP w0.102: U27.AD12 93.92,92.17 93.92,93.24
  TOP w0.112: 93.92,93.24 93.92,93.79 94.51,94.39 94.51,97.54 95.91,98.93 98.17,98.93 111.76,112.52 111.76,133.1 105.49,139.37 105.49,149.28 105.26,149.5 FL8.1
H_HDMI_DY1: length 70.2
  TOP w0.102: U27.AD13 93.25,92.15 93.25,93.22 93.26,93.22 93.26,93.24
  TOP w0.112: FL7.1 101.19,149.5 101.42,149.28 101.42,140.26 109.88,131.8 109.88,113.26 98.05,101.43 97.89,101.43 97.66,101.65 97.21,101.65 96.84,101.29 96.84,100.83 97.07,100.61 97.07,100.45 96.9,100.28 95.84,100.28 93.5,97.94 93.5,95.15 93.26,94.91 93.26,93.24
H_HDMI_DY2: length 71.8
  TOP w0.102: U27.AD15 91.99,92.19 91.99,92.66 92.09,92.75 92.09,93.14 92.04,93.19 92.04,93.3 92.04,93.5 92.04,93.54
  TOP w0.112: FL3.1 98.15,151.54 98.37,151.31 98.37,140 107.57,130.81 107.57,113.53 95.06,101.02 94.9,101.02 94.82,101.1 94.37,101.1 94,100.73 94,100.28 94.08,100.2 94.08,100.04 93.64,99.6 93.48,99.6 93.34,99.74 92.88,99.74 92.52,99.37 92.52,98.92 92.66,98.78 92.66,98.62 92.04,98 92.04,93.64 92.04,93.61 92.04,93.54
H_I2C1_SCL: length 322.9
  TOP w0.127: v2(88.9,51.82) 87.76,51.82 87.47,52.11 U32.35 ; U27.G22 v1(86.79,80.48) ; U28.20 34.35,88.2 v2(34.42,88.26) ; v2(71.88,70.1) 71.88,63.99 71.5,63.61 71.5,62.97 69.98,61.45 69.98,54.23 72.26,51.94 v2(73.03,51.94) ; U26.6 148.6,82.3 v2(148.59,82.3) ; v2(34.54,99.82) 36.28,99.82
  LY3 w0.133: v2(34.29,68.45) 34.29,70.74 34.42,70.87 v2(34.42,88.26) ; v2(73.03,51.94) 74.22,53.14 77.67,53.14 78.86,51.95 81.54,51.95 82.29,52.7 88.02,52.7 v2(88.9,51.82) 89.53,51.82 89.92,51.43 95.13,51.43 95.38,51.18 106.68,51.18 112.91,57.41 143.01,57.41 145.92,60.32 v2(146.94,60.32)
  LY4 w0.133: v2(34.42,88.26) 33.4,89.28 33.4,94.36 34.04,95 34.04,99.31 v2(34.54,99.82) 33.78,100.58 33.78,103.38 45.09,114.68 68.58,114.68 72.9,119 72.9,135.25 75.95,138.3 75.95,158.5 v2(80.77,163.32) ; v2(146.94,60.32) 146.94,60.71 147.7,61.47 147.7,81.41 v2(148.59,82.3) ; v1(86.79,80.48) 82.85,76.55 81.61,76.55 80.36,75.29 78.97,75.29 77.4,73.72 76.65,73.72 75.81,72.87 75.81,72.12 75.23,71.54 74.34,71.54 74.17,71.38 73.43,71.38 72.4,70.36 72.14,70.36 v2(71.88,70.1) 71.46,69.68 71.05,69.68 68.98,67.61 67.75,67.61 67.7,67.56 67.69,67.56 64.29,64.16 55.22,64.16 54.23,65.15 47.88,65.15 47.24,65.79 39.62,65.79 37.59,67.82 34.92,67.82 v2(34.29,68.45)
  BOTTOM w0.127: 35.43,99.82 v2(34.54,99.82) ; R193.2 v2(80.77,163.32)
H_I2C1_SDA: length 322.8
  TOP w0.127: U28.21 v2(34.92,88.84) ; v2(72.52,52.45) 72.16,52.45 70.23,54.38 70.23,61.34 71.75,62.86 71.75,63.5 72.14,63.88 72.14,68.96 72.38,69.2 72.38,70.5 v2(72.01,70.87) ; U26.5 148.1,81.9 v2(148.59,81.41) ; v1(86.14,80.48) U27.G23 ; U22.5 v2(34.54,101.09) ; v2(89.28,52.58) 87.99,52.58 U32.36
  LY3 w0.133: v2(34.92,88.84) v2(34.92,69.09) ; v2(72.52,52.45) 73.53,53.47 78.36,53.47 79.5,52.32 81.15,52.32 81.79,52.96 88.9,52.96 v2(89.28,52.58) 90.17,51.69 95.38,51.69 95.5,51.56 106.43,51.56 112.53,57.67 138.95,57.67 140.84,59.56 144.65,59.56 145.92,60.83 147.19,60.83 v2(147.7,60.32)
  LY4 w0.133: v2(34.92,88.84) 34.92,88.9 33.78,90.04 33.78,93.22 34.67,94.11 34.67,96.9 35.43,97.66 35.43,100.2 v2(34.54,101.09) 34.54,102.36 44.58,112.39 47.5,112.39 48.65,113.54 68.08,113.54 74.3,119.76 74.3,135.89 76.33,137.92 76.33,157.1 79.88,160.66 80.64,160.66 v2(83.31,163.32) ; v1(86.14,80.48) 82.49,76.83 81.4,76.83 80.12,75.55 78.85,75.55 77.33,74.03 76.44,74.03 75.44,73.02 75.44,72.26 74.98,71.8 74.23,71.8 74.07,71.64 73.29,71.64 72.52,70.87 v2(72.01,70.87) 71.87,70.87 68.88,67.87 67.63,67.87 64.18,64.42 55.47,64.42 54.36,65.53 48.01,65.53 47.49,66.05 39.88,66.05 36.84,69.09 v2(34.92,69.09) ; v2(148.59,81.41) 148.08,80.9 148.08,61.21 147.7,60.83 v2(147.7,60.32)
  BOTTOM w0.127: v2(34.54,101.09) 35.43,101.09 ; R192.2 v2(83.31,163.32)
H_I2C5_SCL: length 74.3
  TOP w0.102: U27.B14 92.64,77.24 92.64,76.29 92.71,76.21 92.71,76.17
  TOP w0.127: 92.71,76.17 92.71,72.54 93.47,71.78 93.47,69.98 95.14,68.31 95.14,64.88 96.77,63.25 96.77,58.8 97.28,58.29 97.28,51.31 98.08,50.51 98.08,44.36 97.16,43.43 97.16,40.47 98.17,39.45 98.17,22.69 96.3,20.83 91.19,20.83 v2(90.93,20.57)
  LY3 w0.133: v2(90.93,20.57) 91.06,20.45 91.06,15.87 90.97,15.78 90.97,15.12 91.49,14.6 v2(91.49,14.05)
  BOTTOM w0.127: J19.79 v2(91.49,14.05)
H_I2C5_SDA: length 78.5
  TOP w0.127: v1(91.99,78.53) 92.31,78.86 U27.D14
  LY3 w0.133: v2(87,26.92) 90.3,23.62 90.3,20.19 90.71,19.78 90.71,16.29 90.56,16.14 90.56,14.85 v2(90.89,14.52)
  LY4 w0.102: v1(91.99,78.53) 92.34,78.18 92.34,77.61 91.95,77.22
  LY4 w0.133: 91.95,77.22 91.09,77.22 89.79,75.91 89.79,71.84 v2(91.15,70.48)
  BOTTOM w0.127: v2(91.15,70.48) 91.95,69.68 91.95,66.04 94.61,63.37 94.61,51.82 98.3,48.13 98.3,44.2 99.06,43.43 99.06,39.5 89.66,30.1 89.66,29.59 v2(87,26.92) ; J19.80 v2(90.89,14.52)
H_JTAG_RTCK: length 80.5
  TOP w0.127: v2(121.16,56.52) 120.68,56.04 J14.7 ; v2(67.44,60.74) 67.69,61 67.69,62.74 68.28,63.33 68.28,64.18 67.56,64.9 67.56,73.28 70.87,76.58 72.77,76.58 R70.2
  LY4 w0.133: v2(67.44,60.74) 70.65,60.74 71.06,61.15 77.03,61.15 77.6,61.72 80.01,61.72 80.77,62.48 81.91,62.48 82.17,62.23 115.57,62.23 121.16,56.64 v2(121.16,56.52)
H_JTAG_TCK: length 67
  TOP w0.127: v2(122.05,56.39) 121.68,56.02 J14.3 ; v1(87.44,82.43) U27.K21
  LY3 w0.133: v1(87.44,82.43) 87.44,81.73 87.88,81.28 87.88,80.26 86.74,79.12 86.11,79.12 85.72,78.74 85.72,77.85 86.49,77.09 86.49,73.79 85.72,73.02 85.72,69.34 86.98,68.09 87.76,68.09 88.39,67.46 90.65,67.46 94.87,63.24 94.87,57.06 v2(95.4,56.53)
  LY4 w0.133: v2(122.05,56.39) 122.05,55.88 121.28,55.12 106.93,55.12 105.79,56.26 104.27,56.26 103.52,57.01 95.87,57.01 v2(95.4,56.53)
  BOTTOM w0.127: v2(122.05,56.39) 121.92,56.26 R307.2
H_JTAG_TDI: length 97.6
  TOP w0.127: U27.L23 v1(86.14,83.73) ; J14.5 v2(121.18,55.75) ; v2(66.8,59.82) 66.42,60.2 66.42,69.72 v2(65.91,70.23)
  LY4 w0.133: v2(66.8,59.82) 70.48,59.82 70.61,59.94 71.63,59.94 71.88,59.69 76.07,59.69 77.84,61.46 80.26,61.46 80.9,62.1 81.67,62.1 81.81,61.97 115.07,61.97 121.18,55.85 v2(121.18,55.75) ; v1(86.14,83.73) 83.86,83.73 81.15,81.03 78.11,81.03 73.28,76.2 73.27,76.2 73.26,76.19 73.25,76.19 73.24,76.19 70.6,76.19 66.93,72.52 66.93,71.75 65.91,70.74 v2(65.91,70.23)
H_JTAG_TDO: length 71.3
  TOP w0.127: v2(122.43,46.14) 121.68,46.88 J14.4
  LY3 w0.133: v2(104.27,52.45) 97.92,52.45 94.11,56.25 94.11,63.23 90.4,66.94 88,66.94 87.38,67.56 87.36,67.56 87.36,67.57 86.35,67.57 86.1,67.82 76.69,67.82 75.7,68.81 75.7,73.51 75.56,73.65 v2(75.56,76.33)
  BOTTOM w0.127: R264.2 v2(75.56,76.33) ; v2(104.27,52.45) 105.03,51.69 107.06,51.69 108.97,49.78 114.81,49.78 118.45,46.14 v2(122.43,46.14)
H_JTAG_TMS: length 117.5
  TOP w0.127: J14.2 122.18,47.11 v2(122.43,46.86) ; v2(90.93,41.66) 90.8,41.78 72.01,41.78 71.25,42.54 71.25,45.21 69.72,46.74 69.72,51.05 67.69,53.08 67.69,59.69 66.67,60.71 66.67,69.98 66.48,70.17 v2(66.48,70.68) ; v1(87.44,83.73) U27.L21
  LY3 w0.133: v2(90.93,41.66) 91.44,42.16 94.74,42.16 98.55,45.97 98.55,47.88 100.84,50.17 109.85,50.17 110.49,49.53 119.76,49.53 v2(122.43,46.86)
  LY4 w0.133: v1(87.44,83.73) 86.76,83.06 84.52,83.06 84.51,83.05 84.19,83.05 81.41,80.26 79.38,80.26 76.45,77.34 74.93,77.34 73.41,75.82 70.75,75.82 67.31,72.38 67.31,71.5 v2(66.48,70.68)
  BOTTOM w0.127: v2(122.43,46.86) 122.56,46.99 R328.2
H_JTAG_TRSTN: length 78.5
  TOP w0.127: v1(86.79,83.73) U27.L22
  LY3 w0.133: v2(76.33,77.85) 76.11,77.64 76.11,68.77 76.68,68.2 86.11,68.2 86.47,67.83 87.46,67.83 87.47,67.82 87.48,67.82 88.11,67.2 90.51,67.2 94.37,63.33 94.37,56.5 97.92,52.96 104.65,52.96 v2(105.16,52.45)
  LY4 w0.133: v1(86.79,83.73) 86.37,83.31 83.95,83.31 81.28,80.64 78.36,80.64 76.33,78.61 v2(76.33,77.85)
  BOTTOM w0.127: RJ26.2 117.73,51.31 116.97,50.55 110.62,50.55 108.71,52.45 v2(105.16,52.45)
H_MCASP1_ACLKR_I2C4_SDA: length 88
  TOP w0.127: U27.D16 v1(91.34,78.53) ; R179.1 R173.2 v2(81.91,15.49)
  LY3 w0.133: v1(91.34,78.53) 90.93,78.13 90.93,77.1 92.84,75.19 92.84,69.45 94.09,68.2 95.76,68.2 96.05,67.9 96.05,64.86 97.92,62.99 97.92,60.07 98.68,59.31 98.68,57.4 98.42,57.15 98.42,56.13 v2(98.93,55.63) ; v2(81.91,15.49) 81.91,18.16 82.04,18.29 82.04,20.57 83.06,21.59 v2(83.06,24.64)
  BOTTOM w0.127: v2(98.93,55.63) 98.55,55.24 98.55,53.59 102.62,49.53 102.62,47.37 104.14,45.85 104.14,41.02 99.69,36.58 99.69,31.5 95.12,26.92 90.55,26.92 87.82,24.19 83.5,24.19 v2(83.06,24.64)
H_MCASP1_ACLKX: length 76
  TOP w0.127: v2(74.08,16.68) 75.9,14.86 83.06,14.86 84.45,16.26 88.77,16.26 92.84,20.32 96.65,20.32 98.81,22.48 98.81,39.54 97.79,40.55 97.79,43.31 98.59,44.11 98.59,52.29 97.79,53.09 97.79,57.4 98.46,58.08 98.46,59.02 97.54,59.94 97.54,64.01 96.52,65.02 R103.1
  BOTTOM w0.127: J19.13 v2(74.08,16.68)
H_MCASP1_AXR2: length 85.1
  TOP w0.127: v1(91.99,77.88) U27.C14
  LY3 w0.133: v2(98.93,56.39) 98.93,57.15 99.19,57.4 99.19,59.44 98.28,60.34 98.28,67.2 96.65,68.83 96.13,68.83 96.12,68.84 94.49,68.84 93.37,69.96 93.37,75.67 91.99,77.05 v1(91.99,77.88)
  BOTTOM w0.127: J19.14 74.68,21.2 78.62,25.15 83.31,25.15 83.69,24.76 86.61,24.76 93.09,31.24 94.49,31.24 98.81,35.56 98.81,36.19 103.76,41.15 103.76,45.85 102.36,47.24 102.36,49.28 98.3,53.34 98.3,55.75 v2(98.93,56.39)
H_MCASP1_AXR3: length 84.3
  TOP w0.102: 92.14,76.17 92.14,76.52 91.99,76.66 91.99,77.23 U27.B15
  TOP w0.127: v2(75.31,20.45) 76.33,20.45 76.83,20.95 77.72,20.95 78.11,20.57 89.15,20.57 89.92,21.34 96.09,21.34 97.66,22.91 97.66,39.24 96.65,40.26 96.65,43.69 97.57,44.62 97.57,50.13 96.77,50.93 96.77,57.57 93.9,60.44 93.9,68.79 92.96,69.72 92.96,71.57 91.57,72.96 91.57,74.55 92.14,75.12 92.14,76.17
  BOTTOM w0.127: J19.15 75.28,20.42 v2(75.31,20.45)
H_MCASP1_AXR4: length 83.6
  TOP w0.127: v2(75.95,21.21) 77.83,21.21 78.21,20.83 89.05,20.83 89.81,21.59 95.99,21.59 97.41,23.01 97.41,39.09 96.39,40.11 96.39,43.94 97.32,44.87 97.32,49.89 96.52,50.69 96.52,57.47 93.65,60.34 93.65,68.15 92.71,69.09 92.71,71.46 90.71,73.46 90.71,74.08 91.88,75.25 91.88,76.37 91.66,76.59 U27.A15
  BOTTOM w0.127: J19.16 75.88,21.14 v2(75.95,21.21)
H_MCASP1_AXR5: length 81.2
  TOP w0.127: v2(77.09,20.32) 89.28,20.32 90.04,21.08 96.2,21.08 97.92,22.8 97.92,39.35 96.9,40.36 96.9,43.56 97.83,44.49 97.83,50.38 97.03,51.18 97.03,58.04 96.39,58.67 96.39,62.86 94.2,65.06 94.2,68.87 93.22,69.85 93.22,71.67 92.46,72.43 92.46,76.11 92.39,76.17 92.39,76.83 U27.A14
  BOTTOM w0.127: v2(77.09,20.32) 77.08,20.31 J19.18
H_MCASP1_AXR6: length 80.2
  TOP w0.127: v2(77.47,21.72) 84.33,21.72 84.96,22.35 85.6,22.35 86.36,23.11 87.5,23.11 88.01,22.61 95.57,22.61 96.39,23.43 96.39,38.54 95,39.94 95,55.86 91.69,59.16 91.69,67.56 90.04,69.21 90.04,71.37 89.7,71.72 89.7,74.54 90.2,75.04 90.2,76.48 90.36,76.65 U27.A17
  BOTTOM w0.127: v2(77.47,21.72) 77.68,21.51 J19.19
H_MCASP1_AXR7: length 79.9
  TOP w0.127: v2(78.61,21.25) 84.37,21.25 85.22,22.1 95.78,22.1 96.9,23.22 96.9,38.88 95.88,39.9 95.88,44.17 96.23,44.52 96.23,49.57 96.01,49.78 96.01,57.26 93.09,60.18 93.09,66.04 92.58,66.55 92.58,67.44 90.68,69.34 90.68,71.37 90.93,71.63 90.93,72.52 90.21,73.24 90.21,74.33 91.35,75.48 91.35,76.17 91.01,76.51 U27.A16
  BOTTOM w0.127: J19.20 78.28,20.87 78.61,21.21 v2(78.61,21.25)
H_MCASP1_AXR8: length 78.4
  TOP w0.127: v2(79.5,22.14) 83.22,22.14 84.71,23.62 88.39,23.62 88.9,23.11 95.36,23.11 95.88,23.64 95.88,38.33 94.49,39.73 94.49,55.63 91.19,58.93 91.19,67.31 89.41,69.09 89.41,71.25 88.56,72.09 88.56,73.72 89.19,74.34 89.19,74.75 89.69,75.26 89.69,76.17 89.71,76.2 U27.A18
  BOTTOM w0.127: J19.21 78.89,20.73 79.5,21.34 v2(79.5,22.14)
H_MCASP1_AXR12: length 72.3
  TOP w0.127: RJ30.2 81.91,24.13 88.52,24.13 89.28,23.37 95.25,23.37 95.63,23.75 95.63,38.23 94.23,39.62 94.23,55.5 90.93,58.8 90.93,64.81 89.75,65.99 89.75,67.98 88.9,68.83 88.9,70.99 87.44,72.45 87.44,73.58 88.68,74.82 88.68,74.96 89.06,75.35 U27.A19
H_MCASP1_FSR_I2C4_SCL: length 84.1
  TOP w0.127: v2(72.73,42.67) 74.04,43.98 74.04,52.32 73.03,53.34 72.01,53.34 70.74,54.61 70.74,61.09 72.62,62.97 72.62,63.82 v2(72.79,63.99) ; U27.D17 v1(90.04,78.53) ; v2(80.77,15.49) R174.2 R180.1
  LY3 w0.133: v2(80.77,15.49) 80.77,16.26 78.11,18.92 78.11,30.23 77.09,31.24 77.09,35.31 76.07,36.32 76.07,36.83 72.73,40.17 v2(72.73,42.67)
  LY4 w0.133: v2(72.79,63.99) 74.59,65.79 75.44,65.79 76.07,66.42 76.07,68.82 76.07,68.82 76.07,69.6 76.96,70.48 78.47,70.48 78.47,70.48 81.28,70.48 82.8,72.01 82.92,72.01 82.92,72.01 83.81,72.01 83.81,72.01 84.19,72.01 84.81,72.64 84.81,73 85.09,73.28 85.5,73.28 85.5,73.28 85.98,73.28 89.8,77.1 89.88,77.1 90.42,77.65 90.42,78.15 v1(90.04,78.53)
H_MCASP1_FSX: length 78.1
  TOP w0.127: v2(72.14,43.18) 73.66,44.7 73.66,52.2 72.9,52.96 72.01,52.96 70.48,54.48 70.48,61.19 72.2,62.91 v2(72.2,63.25) ; v1(90.04,77.88) 90.36,78.21 U27.C17
  LY3 w0.133: v2(73.48,21.46) 75.56,23.55 75.56,26.29 76.45,27.18 76.45,32 76.07,32.38 76.07,34.16 75.06,35.18 75.06,37.21 72.14,40.13 v2(72.14,43.18)
  LY4 w0.132: 89.79,77.6 90.04,77.85 v1(90.04,77.88)
  LY4 w0.133: v2(72.2,63.25) 72.2,64.07 74.42,66.29 75.43,66.29 75.81,66.68 75.81,68.93 75.81,68.93 75.81,69.7 76.96,70.85 78.6,70.85 79.32,71.58 80.13,71.58 80.13,71.57 80.91,71.57 80.91,71.58 81.99,71.58 82.68,72.26 82.69,72.26 82.7,72.27 82.81,72.27 82.82,72.27 83.7,72.27 84.08,72.27 84.55,72.74 84.55,73.12 84.97,73.54 85.39,73.54 85.73,73.54 89.79,77.6
  BOTTOM w0.127: J19.12 v2(73.48,21.46)
H_MCASP2_ACLKX: length 63.6
  TOP w0.127: U36.50 29.57,56.37 29.68,56.48 29.68,60.41 TP68.1
  LY4 w0.133: TP68.1 31.75,62.48 39.62,62.48 39.88,62.74 v2(44.41,62.74) 44.62,62.53 48.47,62.53 49.26,61.73 50.56,61.73 51.42,62.6 65.01,62.6 68.45,66.03 73.01,66.03 74.3,67.32 74.3,68.52 74.93,69.15 74.93,69.98 76.71,71.75 77.98,71.75 78.36,72.14 v2(78.36,72.52)
  BOTTOM w0.127: v2(44.41,62.74) 44.41,62.78 44.04,63.15 U55.6 ; R267.1 v2(78.36,72.52)
H_MCASP2_AXR0: length 67.3
  TOP w0.127: v2(43.94,67.69) 43.94,64.9 44.83,64.01 TP73.1 ; U27.A20 88.41,75.41 88.17,75.17 88.17,75.03 86.93,73.78 86.93,72.2 87.7,71.43 87.7,70.16 88.39,69.47 88.39,67.18 88.52,67.06 v2(88.52,66.17)
  LY3 w0.133: v2(88.52,66.17) 87.76,65.41 75.18,65.41 74.8,65.79 72.64,65.79 70.04,68.39 44.64,68.39 v2(43.94,67.69)
  BOTTOM w0.127: U55.3 44.82,61.2 TP73.1
H_MCASP2_AXR1: length 59.5
  TOP w0.102: 89.39,76.17 89.39,77.23 U27.B19
  TOP w0.127: 89.39,76.17 89.39,75.31 88.94,74.86 88.94,74.71 87.7,73.47 87.7,72.58 89.15,71.12 89.15,68.96 90.17,67.95 v2(90.17,66.17)
  BOTTOM w0.127: v2(90.17,66.17) 89.41,65.41 73.03,65.41 67.94,60.32 66.55,60.32 65.91,59.69 60.58,59.69 57.02,63.25 54.23,63.25 52.96,64.52 TP72.1 50.34,63.8 48.89,63.8
H_MCASP2_AXR4: length 79.5
  TOP w0.102: 88.74,76.17 88.74,77.23 U27.B20
  TOP w0.127: v2(89.28,66.17) 89.28,66.93 88.65,67.56 88.65,70.87 87.18,72.33 87.18,73.68 88.43,74.92 88.43,75.07 88.74,75.38 88.74,76.17
  BOTTOM w0.127: 28.57,63.16 38.53,63.16 39.75,64.39 47.37,64.39 48.26,65.28 53.85,65.28 55.5,63.63 57.15,63.63 60.83,59.94 65.81,59.94 67.08,61.21 68.33,61.21 72.77,65.66 88.9,65.66 89.28,66.04 v2(89.28,66.17)
H_MCASP2_AXR5: length 73.2
  TOP w0.127: v1(89.39,77.88) U27.C19
  LY4 w0.132: 89.28,77.6 89.28,77.78 v1(89.39,77.88)
  LY4 w0.133: 89.28,77.6 86.07,74.38 84.92,74.38 84.36,73.82 83.72,73.82 82.81,72.9 82.58,72.9 81.77,72.1 80.69,72.1 78.98,72.1 78.85,72.1 78.12,71.37 76.75,71.37 75.19,69.82 75.19,69.04 74.63,68.48 74.63,67.29 73.11,65.77 68.57,65.77 65.13,62.34 51.53,62.34 50.67,61.47 49.42,61.47 49.42,61.47 48.77,61.47 48.64,61.34 46.1,61.34 45.72,61.72 43.31,61.72 42.42,60.84 31.87,60.84 31.37,61.34 27.18,61.34 v2(27.05,61.21)
  BOTTOM w0.127: 28.57,61.21 v2(27.05,61.21)
H_MCASP2_FSX: length 89.6
  TOP w0.127: U36.48 30.57,59.27 31.24,59.94 31.24,60.2 TP69.1 ; U27.D19 v1(89.43,78.5)
  LY4 w0.133: v2(47.5,61.85) 46.48,61.85 46.06,62.27 40.81,62.27 40,61.47 TP69.1
  BOTTOM w0.102: v1(89.43,78.5) 89.03,78.1 89.03,77.09 88.11,76.17
  BOTTOM w0.127: 88.11,76.17 86.23,74.3 86.23,68.2 87.12,67.31 90.04,67.31 90.8,66.55 90.8,65.91 90.04,65.15 73.28,65.15 67.94,59.82 67.94,59.18 67.44,58.67 62.61,58.67 62.36,58.42 61.34,58.42 56.9,62.86 51.43,62.86 50.42,61.85 v2(47.5,61.85)
H_MCASP3_ACLKX: length 74
  TOP w0.127: v2(86.46,66.76) 86.46,67.34 85.98,67.82 R98.1 ; U36.60 24.57,56.71 TP70.1
  LY3 w0.133: v2(33.91,63.75) 35.69,63.75 41.1,69.17 71.04,69.17 72.43,67.78 73.45,67.78 74,67.22 75.49,67.22 75.53,67.18 75.56,67.18 76.45,66.29 85.99,66.29 v2(86.46,66.76)
  LY4 w0.133: TP70.1 24.38,57.66 26.42,59.69 26.42,61.72 27.81,63.12 33.27,63.12 v2(33.91,63.75)
H_MCASP3_AXR0: length 88.4
  TOP w0.102: U27.B22 86.79,77.23 86.79,76.17
  TOP w0.127: v2(21.21,52.45) 21.53,52.78 U36.67 ; v2(85.47,67.1) 84.71,67.86 84.71,69.6 85.66,70.54 85.66,74.31 85.72,74.38 85.72,74.38 86.79,75.44 86.79,76.17
  LY3 w0.133: v2(34.54,64.35) 39.03,68.83 40.26,68.83 40.85,69.43 72.18,69.43 74.12,67.48 75.59,67.48 75.64,67.44 75.67,67.44 75.68,67.44 75.69,67.44 76.57,66.55 84.93,66.55 v2(85.47,67.1)
  LY4 w0.133: v2(34.54,64.35) 33.23,64.35 32.51,63.63 27.43,63.63 25.91,62.1 25.91,59.94 22.61,56.64 22.61,53.85 v2(21.21,52.45)
H_MCASP3_AXR1: length 82.9
  TOP w0.102: U27.B23 86.46,77.4 86.14,77.07 86.14,76.17
  TOP w0.127: U36.64 21.54,54.28 v2(21.34,54.48) ; 86.14,76.17 86.14,75.6 84.8,74.26 84.8,72.48 84.07,71.75 82.62,71.75 82.17,71.31 82.17,70.62 81.45,69.89 76.5,69.89 76.33,69.72 74.17,69.72 73.41,68.96 v2(73.28,68.96)
  LY4 w0.133: v2(73.28,68.96) 73.51,68.73 73.51,68.31 71.76,66.55 68.22,66.55 64.78,63.12 45.85,63.12 45.04,63.93 43.35,63.93 42.67,63.25 37.34,63.25 35.81,64.77 33.02,64.77 32.26,64.01 26.92,64.01 25.4,62.48 25.4,60.2 21.34,56.13 v2(21.34,54.48)
H_MCASP3_AXR2: length 82
  TOP w0.127: v2(87.4,66.08) 87.63,66.31 87.63,67.31 86.87,68.07 86.87,70.1 86.42,70.55 86.42,73.99 87.67,75.24 87.67,75.38 87.76,75.48 U27.A21
  LY3 w0.133: v2(23.86,60.56) 23.97,60.45 29.72,60.45 30.35,61.09 31.24,61.09 31.5,60.83 33.91,60.83 41.72,68.65 70.16,68.65 72.76,66.05 74.91,66.05 75.29,65.67 86.99,65.67 v2(87.4,66.08)
  BOTTOM w0.127: U56.3 v2(23.86,60.56)
H_MCASP3_AXR3: length 81.7
  TOP w0.102: 87.44,76.17 87.44,77.23 U27.B21
  TOP w0.127: v2(87.12,66.75) 87.12,66.76 87.12,67.18 86.49,67.82 86.49,69.98 86.16,70.3 86.16,74.1 86.36,74.29 86.36,74.3 87.41,75.35 87.41,75.49 87.44,75.52 87.44,76.17
  LY3 w0.133: v2(87.12,66.75) 86.29,65.93 75.4,65.93 75.02,66.31 74.16,66.31 73.03,67.44 72.26,67.44 70.79,68.91 41.35,68.91 34.42,61.98 32.13,61.98 31.5,61.35 30.25,61.35 30.24,61.34 28.96,61.34 28.57,61.72 v2(24.89,61.72)
  BOTTOM w0.127: U56.6 24.1,62.51 v2(24.89,61.72)
H_MCASP3_FSX: length 74.1
  TOP w0.127: U36.59 25.07,56.69 TP71.1 ; U27.A23 86.46,75.54 85.22,74.3 v2(85.22,73.96)
  LY4 w0.133: v2(85.22,73.96) 85.22,73.95 85.06,73.8 84.72,73.8 84.29,73.37 84.29,72.99 83.95,72.64 82.69,72.64 81.88,71.84 80.8,71.84 80.8,71.83 80.24,71.83 80.23,71.84 79.09,71.84 78.37,71.11 76.85,71.11 75.55,69.81 75.55,69.04 75.14,68.62 74.89,68.37 74.89,67.14 73.28,65.53 73.24,65.53 73.22,65.51 71.23,65.51 68.66,62.94 66.12,62.94 65.25,62.08 51.64,62.08 50.58,61.02 49.34,61.02 48.89,60.58 31.5,60.58 30.99,61.08 29.46,61.08 TP71.1
H_MCASP4_ACLKX: length 62.6
  TOP w0.127: v2(42.04,78.49) 42.29,78.23 v2(42.29,64.9) ; R97.1 79.76,70.61 79.55,70.4 76.29,70.4 76.12,70.23 73.53,70.23 v2(73.41,70.36)
  LY4 w0.133: v2(42.29,64.9) 42.67,64.52 43.32,64.52 43.33,64.51 45.19,64.51 46.06,63.64 64.53,63.64 67.98,67.09 69.2,67.09 71.27,69.16 72.21,69.16 v2(73.41,70.36)
  BOTTOM w0.127: v2(42.04,78.49) 41.66,78.87 RJ29.3 40.77,81.03 40.77,82.68 40.39,83.06 39.75,83.06 39.12,83.69 R257.2
H_MCASP4_AXR0: length 84
  TOP w0.127: U27.A24 85.81,75.63 84.54,74.36 84.54,72.73 83.95,72.14 82.64,72.14 81.92,71.42 81.92,70.74 81.32,70.15 76.39,70.15 76.22,69.98 73.83,69.98 v2(73.48,69.63)
  LY3 w0.133: v2(34.04,67.31) 38.23,71.5 38.23,83.95 v2(40.13,85.85)
  LY4 w0.133: v2(73.48,69.63) 73.06,69.63 70.24,66.81 68.08,66.81 64.65,63.38 45.95,63.38 45.15,64.19 41.99,64.19 41.78,64.39 40.39,64.39 37.46,67.31 v2(34.04,67.31)
  BOTTOM w0.127: R253.2 38.86,85.85 v2(40.13,85.85)
H_MCASP4_AXR1: length 78.2
  TOP w0.102: 86.12,78.52 v1(86.14,78.53)
  TOP w0.127: U27.D23 86.12,78.52 ; v2(42.67,84.58) 44.32,84.58 45.34,83.57 45.34,75.44 43.43,73.53 43.43,64.52 44.41,63.54 v2(44.41,63.5)
  LY4 w0.133: v1(86.14,78.53) 86.14,76.25 85.31,75.42 85.08,75.42 84.49,75.42 83.92,74.86 82.44,74.86 81.04,73.46 76.76,73.46 76.07,72.76 76.07,72 73.94,69.87 73.94,67.33 72.9,66.29 68.33,66.29 64.89,62.86 51.3,62.86 50.44,62 49.63,62 48.83,62.79 45.12,62.79 v2(44.41,63.5)
  BOTTOM w0.127: R252.2 v2(42.67,84.58)
